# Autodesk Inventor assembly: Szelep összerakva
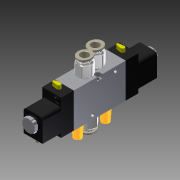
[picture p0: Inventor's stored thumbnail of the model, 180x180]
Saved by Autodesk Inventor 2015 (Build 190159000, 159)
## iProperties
Created: 2013-02
Part Number: Szelep összerakva
Document SubType Name: Assembly
Designer: Marci
Author: Marci
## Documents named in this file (4)
- C:\Users\Andrew Almeida\Documents\Projeto WS2015\WS2015 CAD Data ANLAS\01\Pneumatic System\Engine\Pneumatikus hajtás\Szelep összerakva.iam
- C:\Users\Andrew Almeida\Documents\Projeto WS2015\WS2015 CAD Data ANLAS\01\Pneumatic System\Engine\Pneumatikus hajtás\Szelep.ipt
- C:\Users\Andrew Almeida\Documents\Projeto WS2015\WS2015 CAD Data ANLAS\01\Pneumatic System\Engine\Pneumatikus hajtás\Hangtompító.ipt
- C:\Users\Andrew Almeida\Documents\Projeto WS2015\WS2015 CAD Data ANLAS\01\Pneumatic System\Engine\Pneumatikus hajtás\1.4 12 gyorscsat.ipt
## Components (6 placed, 3 different names)
1. Szelep:1 — Mate:1, Mate:2, Mate:3, Mate:4, Mate:5, Mate:6, Mate:7, Mate:8, Mate:9, Mate:10
2. Hangtompító:1 — Mate:3, Mate:4
3. Hangtompító:2 — Mate:1, Mate:2
4. 1.4 12 gyorscsat:1 — Mate:5, Mate:6
5. 1.4 12 gyorscsat:2 — Mate:7, Mate:9
6. 1.4 12 gyorscsat:3 — Mate:8, Mate:10
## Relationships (10: Mate 10)
- Mate:1: Szelep:1 ↔ Hangtompító:2
- Mate:2: Szelep:1 ↔ Hangtompító:2
- Mate:3: Szelep:1 ↔ Hangtompító:1
- Mate:4: Szelep:1 ↔ Hangtompító:1
- Mate:5: Szelep:1 ↔ 1.4 12 gyorscsat:1
- Mate:6: Szelep:1 ↔ 1.4 12 gyorscsat:1
- Mate:7: Szelep:1 ↔ 1.4 12 gyorscsat:2
- Mate:8: Szelep:1 ↔ 1.4 12 gyorscsat:3
- Mate:9: Szelep:1 ↔ 1.4 12 gyorscsat:2
- Mate:10: Szelep:1 ↔ 1.4 12 gyorscsat:3
